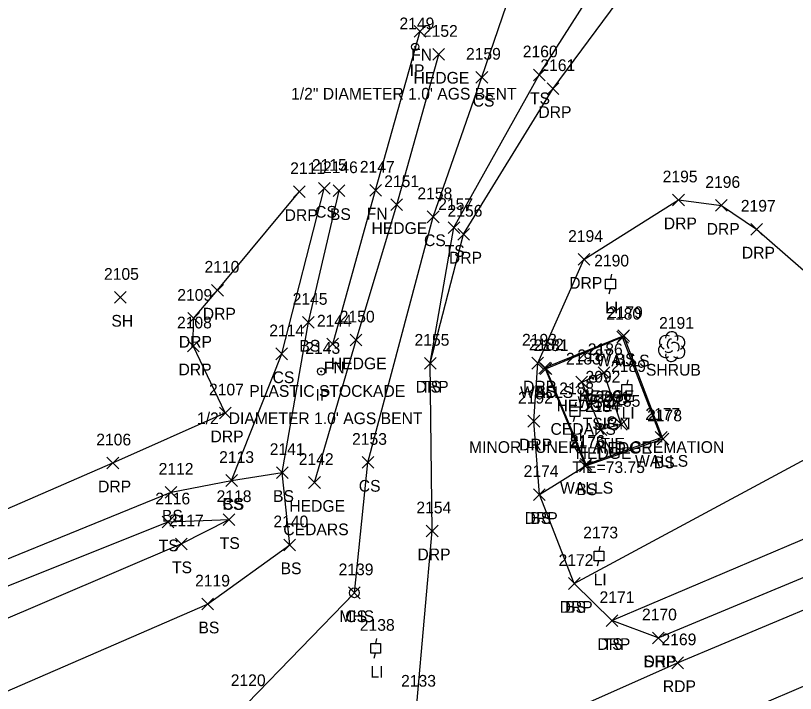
# Model space of a CAD drawing. Extents: x 1477930 to 1480780, y 774090 to 784647.
# Drawn here: x 1478638.5 to 1478771.6, y 774408.9 to 774524.6 of the extents above; entities that cross this region are included whole.
import ezdxf

# ---------------------------------------------------------------- set-up
doc = ezdxf.new("R2010")
doc.units = 0
for name, color, linetype in [('C_A', 7, 'Continuous'), ('C_C', 7, 'Continuous'), ('C_I', 7, 'Continuous'), ('CBP', 7, 'Continuous'), ('L_A', 7, 'Continuous'), ('L_C', 7, 'Continuous'), ('L_I', 7, 'Continuous'), ('L_TIC', 7, 'Continuous'), ('LAHR', 7, 'Continuous'), ('LELB', 7, 'Continuous'), ('LFNC', 7, 'Continuous'), ('LSH', 7, 'Continuous'), ('LWS', 7, 'Continuous'), ('M_A', 7, 'Continuous'), ('M_C', 7, 'Continuous'), ('M_I', 7, 'Continuous'), ('MPIR', 7, 'Continuous'), ('P_A', 7, 'Continuous'), ('P_I', 7, 'Continuous'), ('P_TIC', 7, 'Continuous'), ('PET', 7, 'Continuous'), ('PRC', 7, 'Continuous'), ('PSP', 7, 'Continuous'), ('R_A', 7, 'Continuous'), ('R_I', 7, 'Continuous'), ('R_TIC', 7, 'Continuous'), ('RDP', 7, 'Continuous'), ('S_A', 7, 'Continuous'), ('S_C', 7, 'Continuous'), ('S_I', 7, 'Continuous'), ('SSGN', 7, 'Continuous'), ('U_A', 7, 'Continuous'), ('U_I', 7, 'Continuous'), ('ULP', 7, 'Continuous'), ('USMH', 7, 'Continuous'), ('UWV', 7, 'Continuous')]:
    doc.layers.add(name, color=color, linetype=linetype)

msp = doc.modelspace()

# ---------------------------------------------------------------- linework, layer by layer
at = {"layer": 'CBP'}
for radius in [0.625, 0.0833]:
    msp.add_circle((1478740.25, 774455.57), radius, dxfattribs=at)
at = {"layer": 'L_TIC'}
for points in [[(1478706.54, 774520.98), (1478708.54, 774522.98)], [(1478708.54, 774520.98), (1478706.54, 774522.98)], [(1478709.72, 774517.03), (1478711.72, 774519.03)], [(1478711.72, 774517.03), (1478709.72, 774519.03)], [(1478717.07, 774513.12), (1478719.07, 774515.12)], [(1478719.07, 774513.12), (1478717.07, 774515.12)], [(1478726.88, 774513.52), (1478728.88, 774515.52)], [(1478728.88, 774513.52), (1478726.88, 774515.52)], [(1478690.2, 774494.15), (1478692.2, 774496.15)], [(1478692.2, 774494.15), (1478690.2, 774496.15)], [(1478692.72, 774493.76), (1478694.72, 774495.76)], [(1478694.72, 774493.76), (1478692.72, 774495.76)], [(1478698.95, 774493.84), (1478700.95, 774495.84)], [(1478700.95, 774493.84), (1478698.95, 774495.84)], [(1478702.55, 774491.37), (1478704.55, 774493.37)], [(1478704.55, 774491.37), (1478702.55, 774493.37)], [(1478708.77, 774489.3), (1478710.77, 774491.3)], [(1478710.77, 774489.3), (1478708.77, 774491.3)], [(1478712.32, 774487.47), (1478714.32, 774489.47)], [(1478714.32, 774487.47), (1478712.32, 774489.47)], [(1478655.4, 774475.55), (1478657.4, 774477.55)], [(1478657.4, 774475.55), (1478655.4, 774477.55)], [(1478687.49, 774471.29), (1478689.49, 774473.29)], [(1478689.49, 774471.29), (1478687.49, 774473.29)], [(1478741.28, 774469.01), (1478743.28, 774471.01)], [(1478743.28, 774469.01), (1478741.28, 774471.01)], [(1478695.62, 774468.27), (1478697.62, 774470.27)], [(1478697.62, 774468.27), (1478695.62, 774470.27)], [(1478741.08, 774468.76), (1478743.08, 774470.76)], [(1478743.08, 774468.76), (1478741.08, 774470.76)], [(1478691.64, 774467.57), (1478693.64, 774469.57)], [(1478693.64, 774467.57), (1478691.64, 774469.57)], [(1478682.94, 774465.91), (1478684.94, 774467.91)], [(1478684.94, 774465.91), (1478682.94, 774467.91)], [(1478708.28, 774464.3), (1478710.28, 774466.3)], [(1478710.28, 774464.3), (1478708.28, 774466.3)], [(1478727.81, 774463.5), (1478729.81, 774465.5)], [(1478729.81, 774463.5), (1478727.81, 774465.5)], [(1478728.04, 774463.38), (1478730.04, 774465.38)], [(1478730.04, 774463.38), (1478728.04, 774465.38)], [(1478728.04, 774463.38), (1478730.04, 774465.38)], [(1478730.04, 774463.38), (1478728.04, 774465.38)], [(1478737.9, 774462.7), (1478739.9, 774464.7)], [(1478739.9, 774462.7), (1478737.9, 774464.7)], [(1478737.9, 774462.7), (1478739.9, 774464.7)], [(1478739.9, 774462.7), (1478737.9, 774464.7)], [(1478734.12, 774461.09), (1478736.12, 774463.09)], [(1478736.12, 774461.09), (1478734.12, 774463.09)], [(1478734.12, 774461.09), (1478736.12, 774463.09)], [(1478736.12, 774461.09), (1478734.12, 774463.09)], [(1478740.86, 774453.88), (1478742.86, 774455.88)], [(1478742.86, 774453.88), (1478740.86, 774455.88)], [(1478737.38, 774452.98), (1478739.38, 774454.98)], [(1478739.38, 774452.98), (1478737.38, 774454.98)], [(1478747.66, 774451.64), (1478749.66, 774453.64)], [(1478749.66, 774451.64), (1478747.66, 774453.64)], [(1478747.96, 774451.39), (1478749.96, 774453.39)], [(1478749.96, 774451.39), (1478747.96, 774453.39)], [(1478697.64, 774447.38), (1478699.64, 774449.38)], [(1478699.64, 774447.38), (1478697.64, 774449.38)], [(1478734.74, 774446.79), (1478736.74, 774448.79)], [(1478736.74, 774446.79), (1478734.74, 774448.79)], [(1478734.86, 774447.05), (1478736.86, 774449.05)], [(1478736.86, 774447.05), (1478734.86, 774449.05)], [(1478734.86, 774447.05), (1478736.86, 774449.05)], [(1478736.86, 774447.05), (1478734.86, 774449.05)], [(1478683.02, 774445.64), (1478685.02, 774447.64)], [(1478685.02, 774445.64), (1478683.02, 774447.64)], [(1478683.02, 774445.64), (1478685.02, 774447.64)], [(1478685.02, 774445.64), (1478683.02, 774447.64)], [(1478674.39, 774444.29), (1478676.39, 774446.29)], [(1478676.39, 774444.29), (1478674.39, 774446.29)], [(1478674.39, 774444.29), (1478676.39, 774446.29)], [(1478676.39, 774444.29), (1478674.39, 774446.29)], [(1478688.53, 774443.95), (1478690.53, 774445.95)], [(1478690.53, 774443.95), (1478688.53, 774445.95)], [(1478664.07, 774442.28), (1478666.07, 774444.28)], [(1478666.07, 774442.28), (1478664.07, 774444.28)], [(1478726.89, 774441.89), (1478728.89, 774443.89)], [(1478728.89, 774441.89), (1478726.89, 774443.89)], [(1478663.55, 774437.21), (1478665.55, 774439.21)], [(1478665.55, 774437.21), (1478663.55, 774439.21)], [(1478673.96, 774437.61), (1478675.96, 774439.61)], [(1478675.96, 774437.61), (1478673.96, 774439.61)], [(1478673.96, 774437.61), (1478675.96, 774439.61)], [(1478675.96, 774437.61), (1478673.96, 774439.61)], [(1478665.81, 774433.47), (1478667.81, 774435.47)], [(1478667.81, 774433.47), (1478665.81, 774435.47)], [(1478684.3, 774433.3), (1478686.3, 774435.3)], [(1478686.3, 774433.3), (1478684.3, 774435.3)], [(1478732.85, 774426.71), (1478734.85, 774428.71)], [(1478734.85, 774426.71), (1478732.85, 774428.71)], [(1478695.34, 774425.12), (1478697.34, 774427.12)], [(1478697.34, 774425.12), (1478695.34, 774427.12)], [(1478670.29, 774423.2), (1478672.29, 774425.2)], [(1478672.29, 774423.2), (1478670.29, 774425.2)], [(1478739.27, 774420.37), (1478741.27, 774422.37)], [(1478741.27, 774420.37), (1478739.27, 774422.37)]]:
    msp.add_lwpolyline(points, dxfattribs=at)
at = {"layer": 'LAHR'}
for points in [[(1478689.53, 774444.95), (1478696.62, 774469.27), (1478703.55, 774492.37), (1478710.72, 774518.03)], [(1478735.12, 774462.09), (1478738.38, 774453.98), (1478741.86, 774454.88), (1478738.9, 774463.7)], [(1478735.12, 774462.09), (1478738.9, 774463.7)]]:
    msp.add_lwpolyline(points, dxfattribs=at)
at = {"layer": 'LELB'}
for points in [[(1478740.27, 774421.37), (1478804.49, 774448.68), (1478839.51, 774461.41), (1478900.12, 774482.9), (1478933.76, 774495.55), (1478952.86, 774503.55), (1479014.49, 774533.68), (1479069.06, 774560.68), (1479112.01, 774585.56), (1479167.75, 774622.17), (1479210.47, 774656.8), (1479257.79, 774698.97), (1479291.85, 774733.88), (1479316.96, 774764.31), (1479351.88, 774806.96), (1479375.4, 774842.78), (1479390.8, 774862.22)], [(1478709.28, 774465.3), (1478713.32, 774488.47), (1478727.88, 774514.52), (1478748.26, 774546.58), (1478762.17, 774563.28), (1478765.87, 774581.29)], [(1478636.03, 774390.1), (1478678.02, 774407.2), (1478696.34, 774426.12), (1478698.64, 774448.38), (1478709.77, 774490.3), (1478718.07, 774514.12), (1478731.48, 774553.42)], [(1478675.39, 774445.29), (1478683.94, 774466.91), (1478691.2, 774495.15)], [(1478619, 774424.53), (1478665.07, 774443.28), (1478675.39, 774445.29), (1478684.02, 774446.64), (1478688.49, 774472.29), (1478693.72, 774494.76)], [(1478727.89, 774442.89), (1478735.74, 774447.79), (1478748.96, 774452.39), (1478742.28, 774470.01), (1478728.81, 774464.5)], [(1478733.85, 774427.71), (1478777.91, 774451.45), (1478800.7, 774469.85)], [(1478728.81, 774464.5), (1478735.74, 774447.79)], [(1478628, 774405.4), (1478671.29, 774424.2), (1478685.3, 774434.3), (1478684.02, 774446.64)], [(1478620.84, 774420.79), (1478664.55, 774438.21), (1478674.96, 774438.61)], [(1478622.98, 774415.76), (1478666.81, 774434.47), (1478674.96, 774438.61)]]:
    msp.add_lwpolyline(points, dxfattribs=at)
at = {"layer": 'LFNC'}
msp.add_lwpolyline([(1478692.64, 774468.57), (1478699.95, 774494.84), (1478707.54, 774521.98)], dxfattribs=at)
at = {"layer": 'LSH'}
msp.add_line((1478750.44, 774468.19), (1478750.44, 774468.19), dxfattribs=at)
msp.add_line((1478750.44, 774468.19), (1478750.44, 774468.19), dxfattribs=at)
msp.add_arc((1478750.48, 774469.63), 1.05, 335.5272, 180.9563, dxfattribs=at)
for centre, major_axis, ratio, start_param, end_param in [((1478749.65, 774468.86), (1.21, -0.51), 0.895232, 1.570796, 4.712389), ((1478751.48, 774468.78), (-1.14, -0.48), 0.949671, 1.570796, 4.712389), ((1478749.35, 774467.48), (0.58, -1.04), 0.959034, 3.141593, 6.283185), ((1478750.23, 774468.65), (-0.208, -0.792), 0.645439, 3.141593, 6.283185), ((1478750.94, 774468.03), (-0.5, 0.667), 0.989748, 3.141593, 6.283185), ((1478749.98, 774467.44), (-0.625, -0.083), 0.423636, 0, 3.141593), ((1478751.44, 774467.36), (-1.09, 0.79), 0.841452, 1.570796, 4.712389), ((1478750.44, 774466.69), (0.26, 1.06), 0.942809, 1.570796, 4.712389)]:
    msp.add_ellipse(centre, major_axis=major_axis, ratio=ratio, start_param=start_param, end_param=end_param, dxfattribs=at)
at = {"layer": 'LWS'}
for points in [[(1478735.86, 774448.05), (1478748.66, 774452.64), (1478742.08, 774469.76), (1478729.04, 774464.38)], [(1478735.86, 774448.05), (1478729.04, 774464.38)]]:
    msp.add_lwpolyline(points, dxfattribs=at)
at = {"layer": 'MPIR'}
for centre, radius in [((1478706.72, 774519.31), 0.625), ((1478706.72, 774519.31), 0.0833), ((1478690.67, 774463.91), 0.625), ((1478690.67, 774463.91), 0.0833)]:
    msp.add_circle(centre, radius, dxfattribs=at)
at = {"layer": 'P_TIC'}
for points in [[(1478747.16, 774417.42), (1478749.16, 774419.42)], [(1478749.16, 774417.42), (1478747.16, 774419.42)], [(1478750.46, 774413.17), (1478752.46, 774415.17)], [(1478752.46, 774413.17), (1478750.46, 774415.17)]]:
    msp.add_lwpolyline(points, dxfattribs=at)
at = {"layer": 'PET'}
msp.add_lwpolyline([(1478646.9, 774367.62), (1478687.83, 774385.99), (1478707.1, 774394.45), (1478751.46, 774414.17), (1478808.39, 774438.04), (1478858.43, 774458.78), (1478902.75, 774477.06), (1478935.49, 774490.35), (1478955.71, 774499.82), (1478999.73, 774519.88), (1479070.74, 774558.33), (1479113.57, 774583.69), (1479168.73, 774620.31), (1479212.4, 774655.38)], dxfattribs=at)
at = {"layer": 'PRC'}
msp.add_lwpolyline([(1478650.81, 774357.08), (1478692.43, 774375.46), (1478727.16, 774390.64), (1478811.24, 774426.58)], dxfattribs=at)
at = {"layer": 'PSP'}
msp.add_lwpolyline([(1478748.16, 774418.42), (1478806.27, 774442.6), (1478856.23, 774463.3), (1478900.95, 774480.92), (1478934.33, 774492.77), (1478954.52, 774501.85), (1478998.69, 774521.94), (1479070.74, 774558.33)], dxfattribs=at)
at = {"layer": 'R_TIC'}
for points in [[(1478729.23, 774511.18), (1478731.23, 774513.18)], [(1478731.23, 774511.18), (1478729.23, 774513.18)], [(1478685.94, 774493.59), (1478687.94, 774495.59)], [(1478687.94, 774493.59), (1478685.94, 774495.59)], [(1478750.62, 774492.18), (1478752.62, 774494.18)], [(1478752.62, 774492.18), (1478750.62, 774494.18)], [(1478757.93, 774491.24), (1478759.93, 774493.24)], [(1478759.93, 774491.24), (1478757.93, 774493.24)], [(1478713.97, 774486.33), (1478715.97, 774488.33)], [(1478715.97, 774486.33), (1478713.97, 774488.33)], [(1478763.94, 774487.18), (1478765.94, 774489.18)], [(1478765.94, 774487.18), (1478763.94, 774489.18)], [(1478734.49, 774482.02), (1478736.49, 774484.02)], [(1478736.49, 774482.02), (1478734.49, 774484.02)], [(1478671.98, 774476.77), (1478673.98, 774478.77)], [(1478673.98, 774476.77), (1478671.98, 774478.77)], [(1478667.9, 774471.97), (1478669.9, 774473.97)], [(1478669.9, 774471.97), (1478667.9, 774473.97)], [(1478667.84, 774467.25), (1478669.84, 774469.25)], [(1478669.84, 774467.25), (1478667.84, 774469.25)], [(1478708.28, 774464.3), (1478710.28, 774466.3)], [(1478710.28, 774464.3), (1478708.28, 774466.3)], [(1478726.62, 774464.32), (1478728.62, 774466.32)], [(1478728.62, 774464.32), (1478726.62, 774466.32)], [(1478673.3, 774455.82), (1478675.3, 774457.82)], [(1478675.3, 774455.82), (1478673.3, 774457.82)], [(1478725.94, 774454.42), (1478727.94, 774456.42)], [(1478727.94, 774454.42), (1478725.94, 774456.42)], [(1478654.13, 774447.28), (1478656.13, 774449.28)], [(1478656.13, 774447.28), (1478654.13, 774449.28)], [(1478726.89, 774441.89), (1478728.89, 774443.89)], [(1478728.89, 774441.89), (1478726.89, 774443.89)], [(1478708.6, 774435.68), (1478710.6, 774437.68)], [(1478710.6, 774435.68), (1478708.6, 774437.68)], [(1478732.85, 774426.71), (1478734.85, 774428.71)], [(1478734.85, 774426.71), (1478732.85, 774428.71)], [(1478739.27, 774420.37), (1478741.27, 774422.37)], [(1478741.27, 774420.37), (1478739.27, 774422.37)], [(1478747.16, 774417.42), (1478749.16, 774419.42)], [(1478749.16, 774417.42), (1478747.16, 774419.42)]]:
    msp.add_lwpolyline(points, dxfattribs=at)
at = {"layer": 'RDP'}
for points in [[(1478748.16, 774418.42), (1478740.27, 774421.37), (1478733.85, 774427.71), (1478727.89, 774442.89), (1478726.94, 774455.42), (1478727.62, 774465.32), (1478735.49, 774483.02), (1478751.62, 774493.18), (1478758.93, 774492.24), (1478764.94, 774488.18), (1478777.36, 774477.34), (1478789.43, 774470.73), (1478800.7, 774469.85), (1478846.18, 774488.25), (1478890.08, 774507.83), (1478919.43, 774520.57), (1478935.27, 774529.68), (1478950.09, 774542.89), (1478954.57, 774561.42), (1478952.25, 774573.68), (1478933.77, 774618.29)], [(1478703.21, 774398.11), (1478707, 774407.1), (1478709.6, 774436.68), (1478709.28, 774465.3), (1478714.97, 774487.33), (1478730.23, 774512.18), (1478752.1, 774541.74), (1478767.16, 774553.47), (1478789.48, 774563.65), (1478796.27, 774564.29)], [(1478615.49, 774431.05), (1478655.13, 774448.28), (1478674.3, 774456.82), (1478668.84, 774468.25), (1478668.9, 774472.97), (1478672.98, 774477.77), (1478686.94, 774494.59)]]:
    msp.add_lwpolyline(points, dxfattribs=at)
at = {"layer": 'SSGN'}
for p, q in [((1478735.08, 774459.92), (1478743.67, 774459.92)), ((1478739.1, 774459.02), (1478739.1, 774459.02))]:
    msp.add_line(p, q, dxfattribs=at)
for centre in [(1478736.74, 774459.09), (1478741.95, 774459.02)]:
    msp.add_circle(centre, 0.833, dxfattribs=at)
at = {"layer": 'ULP'}
for p, q in [((1478740.19, 774480.5), (1478740.02, 774479.66)), ((1478739.19, 774478), (1478739.19, 774479.66)), ((1478739.19, 774479.66), (1478740.85, 774479.66)), ((1478740.85, 774479.66), (1478740.85, 774478)), ((1478740.85, 774478), (1478739.19, 774478)), ((1478739.77, 774477.16), (1478740.02, 774478)), ((1478740.02, 774478.83), (1478740.02, 774478.83)), ((1478741.98, 774459.98), (1478741.98, 774461.65)), ((1478741.98, 774461.65), (1478743.65, 774461.65)), ((1478742.98, 774462.48), (1478742.82, 774461.65)), ((1478743.65, 774461.65), (1478743.65, 774459.98)), ((1478742.82, 774460.82), (1478742.82, 774460.82)), ((1478743.65, 774459.98), (1478741.98, 774459.98)), ((1478742.57, 774459.15), (1478742.82, 774459.98)), ((1478733.13, 774456.19), (1478733.13, 774457.86)), ((1478733.13, 774457.86), (1478734.79, 774457.86)), ((1478734.13, 774458.69), (1478733.96, 774457.86)), ((1478734.79, 774457.86), (1478734.79, 774456.19)), ((1478733.96, 774457.02), (1478733.96, 774457.02)), ((1478734.79, 774456.19), (1478733.13, 774456.19)), ((1478733.71, 774455.36), (1478733.96, 774456.19)), ((1478738.22, 774434.08), (1478738.05, 774433.25)), ((1478737.22, 774431.58), (1478737.22, 774433.25)), ((1478737.22, 774433.25), (1478738.88, 774433.25)), ((1478738.05, 774432.41), (1478738.05, 774432.41)), ((1478738.88, 774433.25), (1478738.88, 774431.58)), ((1478738.88, 774431.58), (1478737.22, 774431.58)), ((1478737.8, 774430.75), (1478738.05, 774431.58)), ((1478700.12, 774418.31), (1478699.95, 774417.47)), ((1478699.12, 774415.81), (1478699.12, 774417.47)), ((1478699.12, 774417.47), (1478700.79, 774417.47)), ((1478699.95, 774416.64), (1478699.95, 774416.64)), ((1478700.79, 774417.47), (1478700.79, 774415.81)), ((1478700.79, 774415.81), (1478699.12, 774415.81)), ((1478699.7, 774414.97), (1478699.95, 774415.81))]:
    msp.add_line(p, q, dxfattribs=at)
at = {"layer": 'USMH'}
for p, q in [((1478696.34, 774426.12), (1478696.34, 774426.12)), ((1478697.17, 774426.12), (1478697.17, 774426.12))]:
    msp.add_line(p, q, dxfattribs=at)
msp.add_circle((1478696.34, 774426.12), 0.833, dxfattribs=at)
at = {"layer": 'UWV'}
for radius in [0.625, 0.0833]:
    msp.add_circle((1478737.07, 774462.66), radius, dxfattribs=at)

# ---------------------------------------------------------------- texts
at = {"layer": 'C_A'}
msp.add_text('TIE', height=2, dxfattribs=at).set_placement((1478738.33, 774450.57))
at = {"layer": 'C_C'}
msp.add_text('TIE=73.75', height=2, dxfattribs=at).set_placement((1478733.48, 774446.57))
at = {"layer": 'C_I'}
msp.add_text('2091', height=2, dxfattribs=at).set_placement((1478737.48, 774458.57))
at = {"layer": 'L_A'}
for s, p in [('FN', (1478706.02, 774516.98)), ('HEDGE', (1478706.42, 774513.03)), ('CS', (1478716.51, 774509.12)), ('TS', (1478726.29, 774509.52)), ('CS', (1478689.64, 774490.15)), ('BS', (1478692.16, 774489.76)), ('FN', (1478698.43, 774489.84)), ('HEDGE', (1478699.25, 774487.37)), ('CS', (1478708.21, 774485.3)), ('TS', (1478711.73, 774483.47)), ('SH', (1478654.88, 774471.55)), ('BS', (1478686.94, 774467.29)), ('BS', (1478740.72, 774465.01)), ('HEDGE', (1478692.32, 774464.27)), ('WALLS', (1478737.62, 774464.76)), ('FN', (1478691.12, 774463.57)), ('SHRUB', (1478746.07, 774463.19)), ('CS', (1478682.38, 774461.91)), ('TS', (1478707.69, 774460.3)), ('WALLS', (1478724.59, 774459.38)), ('WALLS', (1478724.59, 774459.38)), ('BS', (1478727.25, 774459.5)), ('HEDGE', (1478734.6, 774458.7)), ('HEDGE', (1478734.6, 774458.7)), ('HEDGE', (1478730.82, 774457.09)), ('HEDGE', (1478730.82, 774457.09)), ('HEDGE', (1478734.08, 774448.98)), ('HEDGE', (1478737.56, 774449.88)), ('WALLS', (1478744.2, 774447.64)), ('BS', (1478747.41, 774447.39)), ('CS', (1478697.08, 774443.38)), ('WALLS', (1478731.41, 774443.05)), ('WALLS', (1478731.41, 774443.05)), ('BS', (1478734.18, 774442.79)), ('BS', (1478682.46, 774441.64)), ('BS', (1478682.46, 774441.64)), ('CS', (1478673.83, 774440.29)), ('BS', (1478673.83, 774440.29)), ('HEDGE', (1478685.23, 774439.95)), ('BS', (1478663.51, 774438.28)), ('BS', (1478726.33, 774437.89)), ('TS', (1478662.96, 774433.21)), ('TS', (1478673.37, 774433.61)), ('TS', (1478673.37, 774433.61)), ('TS', (1478665.22, 774429.47)), ('BS', (1478683.75, 774429.3)), ('BS', (1478732.29, 774422.71)), ('CS', (1478694.78, 774421.12)), ('BS', (1478669.73, 774419.2)), ('TS', (1478738.68, 774416.37))]:
    msp.add_text(s, height=2, dxfattribs=at).set_placement(p)
at = {"layer": 'L_C'}
for s, p in [('PLASTIC STOCKADE', (1478678.4, 774459.57)), ('CEDARS', (1478729.79, 774453.09)), ('CEDARS', (1478729.79, 774453.09)), ('CEDARS', (1478684.21, 774435.95))]:
    msp.add_text(s, height=2, dxfattribs=at).set_placement(p)
at = {"layer": 'L_I'}
for s, p in [('2152', (1478708.02, 774521.03)), ('2159', (1478715.37, 774517.12)), ('2160', (1478725.06, 774517.52)), ('2115', (1478689.08, 774498.15)), ('2146', (1478690.97, 774497.76)), ('2147', (1478697.26, 774497.84)), ('2151', (1478701.42, 774495.37)), ('2158', (1478707.08, 774493.3)), ('2157', (1478710.63, 774491.47)), ('2105', (1478653.62, 774479.55)), ('2145', (1478685.8, 774475.29)), ('2179', (1478739.58, 774473.01)), ('2150', (1478693.84, 774472.27)), ('2180', (1478739.3, 774472.76)), ('2144', (1478689.94, 774471.57)), ('2191', (1478748.31, 774471.19)), ('2114', (1478681.81, 774469.91)), ('2155', (1478706.59, 774468.3)), ('2182', (1478726.11, 774467.5)), ('2181', (1478726.92, 774467.38)), ('2181', (1478726.92, 774467.38)), ('2186', (1478736.15, 774466.7)), ('2186', (1478736.15, 774466.7)), ('2183', (1478732.42, 774465.09)), ('2183', (1478732.42, 774465.09)), ('2184', (1478735.69, 774456.98)), ('2185', (1478739.17, 774457.88)), ('2177', (1478745.96, 774455.64)), ('2178', (1478746.27, 774455.39)), ('2153', (1478695.94, 774451.38)), ('2175', (1478733.05, 774450.79)), ('2176', (1478733.12, 774451.05)), ('2176', (1478733.12, 774451.05)), ('2141', (1478681.89, 774449.64)), ('2141', (1478681.89, 774449.64)), ('2113', (1478673.26, 774448.29)), ('2113', (1478673.26, 774448.29)), ('2142', (1478686.84, 774447.95)), ('2112', (1478662.94, 774446.28)), ('2174', (1478725.2, 774445.89)), ('2116', (1478662.37, 774441.21)), ('2118', (1478672.83, 774441.61)), ('2118', (1478672.83, 774441.61)), ('2117', (1478664.68, 774437.47)), ('2140', (1478682.52, 774437.3)), ('2172', (1478731.16, 774430.71)), ('2139', (1478693.64, 774429.12)), ('2119', (1478669.16, 774427.2)), ('2171', (1478738.15, 774424.37)), ('2120', (1478675.24, 774410.2)), ('2133', (1478704.3, 774410.1))]:
    msp.add_text(s, height=2, dxfattribs=at).set_placement(p)
at = {"layer": 'M_A'}
for p in [(1478705.76, 774514.31), (1478689.71, 774458.91)]:
    msp.add_text('IP', height=2, dxfattribs=at).set_placement(p)
at = {"layer": 'M_C'}
for p in [(1478685.53, 774510.31), (1478669.48, 774454.91)]:
    msp.add_text('1/2" DIAMETER 1.0\' AGS BENT', height=2, dxfattribs=at).set_placement(p)
at = {"layer": 'M_I'}
for s, p in [('2149', (1478704.02, 774522.31)), ('2143', (1478687.97, 774466.91))]:
    msp.add_text(s, height=2, dxfattribs=at).set_placement(p)
at = {"layer": 'P_A'}
for s, p in [('SHP', (1478745.7, 774413.42)), ('RDP', (1478748.95, 774409.17))]:
    msp.add_text(s, height=2, dxfattribs=at).set_placement(p)
at = {"layer": 'P_I'}
for s, p in [('2170', (1478745.39, 774421.42)), ('2169', (1478748.72, 774417.17))]:
    msp.add_text(s, height=2, dxfattribs=at).set_placement(p)
at = {"layer": 'R_A'}
for p in [(1478727.72, 774507.18), (1478684.43, 774489.59), (1478749.11, 774488.18), (1478756.42, 774487.24), (1478712.46, 774482.33), (1478762.43, 774483.18), (1478732.98, 774478.02), (1478670.47, 774472.77), (1478666.39, 774467.97), (1478666.33, 774463.25), (1478706.77, 774460.3), (1478725.11, 774460.32), (1478671.79, 774451.82), (1478724.43, 774450.42), (1478652.61, 774443.28), (1478725.38, 774437.89), (1478707.09, 774431.68), (1478731.34, 774422.71), (1478737.76, 774416.37), (1478745.65, 774413.42)]:
    msp.add_text('DRP', height=2, dxfattribs=at).set_placement(p)
at = {"layer": 'R_I'}
for s, p in [('2161', (1478728.06, 774515.18)), ('2111', (1478685.38, 774497.59)), ('2195', (1478748.92, 774496.18)), ('2196', (1478756.19, 774495.24)), ('2156', (1478712.22, 774490.33)), ('2197', (1478762.25, 774491.18)), ('2194', (1478732.79, 774486.02)), ('2110', (1478670.77, 774480.77)), ('2109', (1478666.12, 774475.97)), ('2108', (1478666.07, 774471.25)), ('2155', (1478706.59, 774468.3)), ('2193', (1478724.93, 774468.32)), ('2107', (1478671.53, 774459.82)), ('2192', (1478724.24, 774458.42)), ('2106', (1478652.3, 774451.28)), ('2174', (1478725.2, 774445.89)), ('2154', (1478706.91, 774439.68)), ('2172', (1478731.16, 774430.71)), ('2171', (1478738.15, 774424.37)), ('2170', (1478745.39, 774421.42)), ('2133', (1478704.3, 774410.1))]:
    msp.add_text(s, height=2, dxfattribs=at).set_placement(p)
at = {"layer": 'S_A'}
msp.add_text('TSIGN', height=2, dxfattribs=at).set_placement((1478735.27, 774454))
at = {"layer": 'S_C'}
msp.add_text('MINOR FUNERL AND CREMATION', height=2, dxfattribs=at).set_placement((1478715.89, 774450))
at = {"layer": 'S_I'}
msp.add_text('2092', height=2, dxfattribs=at).set_placement((1478735.75, 774462))
at = {"layer": 'U_A'}
for s, p in [('LI', (1478739.12, 774473.83)), ('WSO', (1478734.4, 774457.66)), ('LI', (1478741.92, 774455.82)), ('LI', (1478733.06, 774452.02)), ('LI', (1478737.15, 774427.41)), ('MHS', (1478693.76, 774421.12)), ('LI', (1478699.06, 774411.64))]:
    msp.add_text(s, height=2, dxfattribs=at).set_placement(p)
at = {"layer": 'U_I'}
for s, p in [('2190', (1478737.24, 774481.83)), ('2187', (1478734.37, 774465.66)), ('2189', (1478740.12, 774463.82)), ('2188', (1478731.27, 774460.02)), ('2173', (1478735.36, 774435.41)), ('2139', (1478693.64, 774429.12)), ('2138', (1478697.26, 774419.64))]:
    msp.add_text(s, height=2, dxfattribs=at).set_placement(p)

doc.saveas('drawing.dxf')
